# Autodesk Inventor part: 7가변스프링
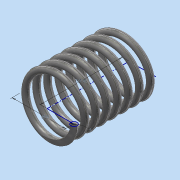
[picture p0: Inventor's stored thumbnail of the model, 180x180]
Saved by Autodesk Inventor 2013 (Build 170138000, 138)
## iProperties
Created: 2014-12
Part Number: 7가변스프링
Material: 강철, 탄소
Document SubType Name: Modeling
Designer: 교육생
Density: 7.87 g/cm^3
Mass: 80.1302 g
Surface Area: 103.217 cm^2
Volume: 10.1817 cm^3
Author: 교육생
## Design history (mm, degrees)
sketch "스케치1"
  geometry: L1 (0, 0)-(17.5, 0); L2 (0, 0)-(0, 48.5); L3 (0, 48.5)-(17.5, 48.5); C1 r 2 at (17.5, 0)
  constraints: 6 end point, 2 perpendicular, 1 centre point, 1 coincident, 1 horizontal, 1 parallel
  dimensions: "d0" = 4 diameter of C1; "d2" = 35 diameter of L1.end L2; "d3" = 48.5 distance of L1.start L2.end (derived)
feature "코일1" sketch "스케치1" pitch "d4" = 10; turns "d6" = 7.5; dims "d5" = 48.50005 (computed from d3), "d7" = 0, angle "d8" = 90 deg, angle "d9" = 90 deg, "d10" = 0, "d11" = 0
node "작업 평면1"
feature "분할1"
feature "분할2"
node "솔리드1"
other parameters: "d12" = 0
